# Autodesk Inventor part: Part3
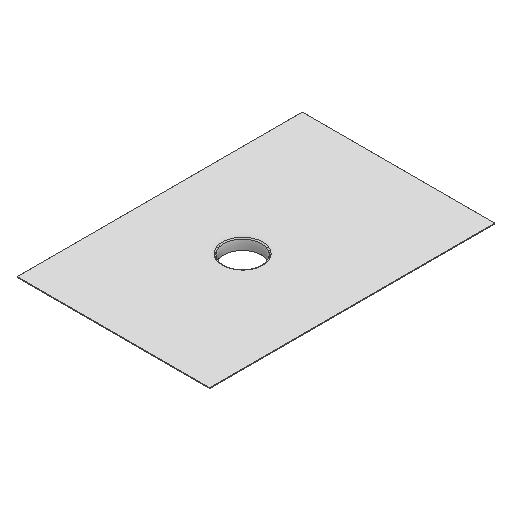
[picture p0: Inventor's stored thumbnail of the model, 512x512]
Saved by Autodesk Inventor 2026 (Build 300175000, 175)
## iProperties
Created: 2025-03
Part Number: Part3
Material: Generic
Document SubType Name: Sheet Metal
Designer: zhangy5
Density: 1 g/cm^3
Sheet Metal Rule: Default_mm
Appearance: Default
Author: zhangy5
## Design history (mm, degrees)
node "Face1"
  sketch "Sketch1"
    geometry: L1 (59.917, 85.629)-(-64.398, 85.629); L2 (-64.398, 85.629)-(-64.398, -98.534); L3 (-64.398, -98.534)-(59.917, -98.534); L4 (59.917, -98.534)-(59.917, 85.629); 1 further point
    constraints: 8 end point, 2 parallel, 1 horizontal, 1 perpendicular
workplane "Work Plane1"
sketch "Sketch3"
  geometry: C1 r 12.7 at (0, 0); 1 further point
  constraints: 1 centre point, 1 coincident
  dimensions: "Diameter" = 25.4 diameter of C1
extrude "Extrusion2" join sketch "Sketch3" taper "d6" = 0 deg; distance "Height" = 6.35
sketch "Sketch4"
  geometry: C1 r 12.2 at (0, 0)
  constraints: 1 centre point
  dimensions: "d7" = 24.4 diameter of C1 (= Diameter - 2 x Thickness)
extrude "Extrusion3" cut sketch "Sketch4" distance "d8" = 6.85 (= Height + Thickness); taper "d9" = 0 deg
sketch "Sketch5"
  geometry: C1 r 12.2 at (0, 0); 1 further point
  constraints: 1 centre point, 1 coincident
  dimensions: "d17" = 24.4 diameter of C1 (= d7)
extrude "Extrusion4" cut sketch "Sketch5" distance "d15" = 0.5 (= Thickness); taper "Angle" = 60 deg
chamfer "Chamfer3" distance "d21" = 0.25 (= 0.5 x Thickness); stored, may be unused: second distance "d22" = 3.175, angle "d23" = 30 deg (computed from Angle)
body "Solid1"
face "Plate1" dims "d0" = 0.5 (= Thickness)
other parameters: "Thickness" = 0.5 (derived), "BendRadius" = 0.5 (= Thickness), "BendReliefWidth" = 0.5 (= Thickness), "BendReliefDepth" = 0.25 (= 0.5 x Thickness), "CornerReliefSize" = 2 (= 4 x Thickness), "SeamGap" = 0.00508, "MinimumRemnant" = 1 (= 2 x Thickness), "TransitionRadius" = 0.5 (= BendRadius), "JacobiRadiusSize" = 0.5 (= BendRadius), "GapSize" = 0.5 (= Thickness), "d13" = -0.5 (= -Thickness)
